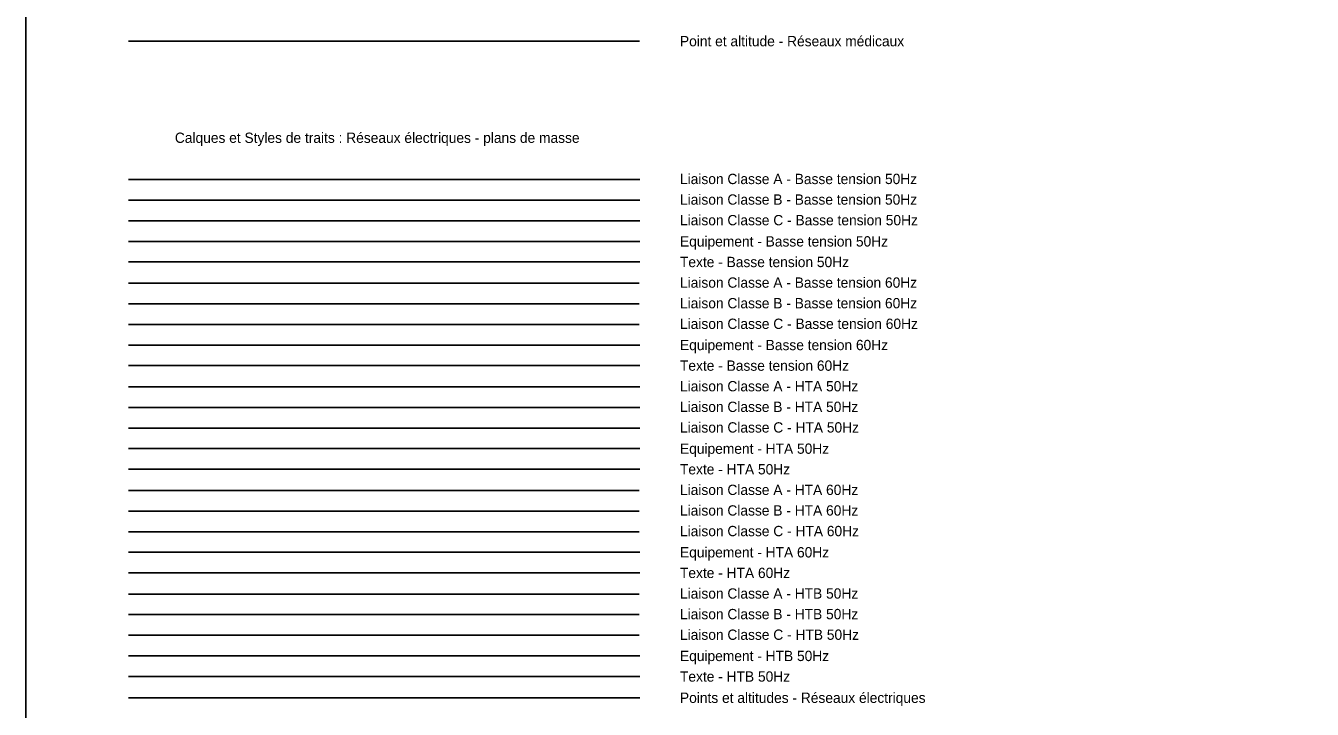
# Model space of a CAD drawing. Extents: x 703432 to 707394, y 7057985 to 7059523.
# Drawn here: x 707199.5 to 707262, y 7058568.9 to 7058602.1 of the extents above; entities that cross this region are included whole.
import ezdxf

# ---------------------------------------------------------------- set-up
doc = ezdxf.new("R2010")
doc.units = 0
for name, color, linetype in [('DH_CADRE -CARTOUCHE', 7, 'Continuous'), ('R_ELEC_ALT_POINT', 7, 'Continuous'), ('R_ELEC_BT_50HZ_EQUIP', 7, 'Continuous'), ('R_ELEC_BT_50HZ_LIAISON_CL_A', 7, 'Continuous'), ('R_ELEC_BT_50HZ_LIAISON_CL_B', 7, 'Continuous'), ('R_ELEC_BT_50HZ_LIAISON_CL_C', 7, 'Continuous'), ('R_ELEC_BT_50HZ_TEXTE', 7, 'Continuous'), ('R_ELEC_BT_60HZ_EQUIP', 7, 'Continuous'), ('R_ELEC_BT_60HZ_LIAISON_CL_A', 7, 'Continuous'), ('R_ELEC_BT_60HZ_LIAISON_CL_B', 7, 'Continuous'), ('R_ELEC_BT_60HZ_LIAISON_CL_C', 7, 'Continuous'), ('R_ELEC_BT_60HZ_TEXTE', 7, 'Continuous'), ('R_ELEC_HTA_50HZ_EQUIP', 7, 'Continuous'), ('R_ELEC_HTA_50HZ_LIAISON_CL_A', 7, 'Continuous'), ('R_ELEC_HTA_50HZ_LIAISON_CL_B', 7, 'Continuous'), ('R_ELEC_HTA_50HZ_LIAISON_CL_C', 7, 'Continuous'), ('R_ELEC_HTA_50HZ_TEXTE', 7, 'Continuous'), ('R_ELEC_HTA_60HZ_EQUIP', 7, 'Continuous'), ('R_ELEC_HTA_60HZ_LIAISON_CL_A', 7, 'Continuous'), ('R_ELEC_HTA_60HZ_LIAISON_CL_B', 7, 'Continuous'), ('R_ELEC_HTA_60HZ_LIAISON_CL_C', 7, 'Continuous'), ('R_ELEC_HTA_60HZ_TEXTE', 7, 'Continuous'), ('R_ELEC_HTB_50HZ_EQUIP', 7, 'Continuous'), ('R_ELEC_HTB_50HZ_LIAISON_CL_A', 7, 'Continuous'), ('R_ELEC_HTB_50HZ_LIAISON_CL_B', 7, 'Continuous'), ('R_ELEC_HTB_50HZ_LIAISON_CL_C', 7, 'Continuous'), ('R_ELEC_HTB_50HZ_TEXTE', 7, 'Continuous'), ('R_MED_ALT_POINT', 7, 'Continuous')]:
    doc.layers.add(name, color=color, linetype=linetype)

msp = doc.modelspace()

# ---------------------------------------------------------------- linework, layer by layer
at = {"layer": 'DH_CADRE -CARTOUCHE'}
msp.add_lwpolyline([(707199.469, 7058644.551), (707324.469, 7058644.551), (707324.469, 7058419.551), (707199.469, 7058419.551)], close=True, dxfattribs=at)
at = {"layer": 'R_ELEC_ALT_POINT'}
msp.add_line((707204.469, 7058569.453), (707229.298, 7058569.453), dxfattribs=at)
at = {"layer": 'R_ELEC_BT_50HZ_EQUIP'}
msp.add_line((707204.469, 7058591.608), (707229.298, 7058591.608), dxfattribs=at)
at = {"layer": 'R_ELEC_BT_50HZ_LIAISON_CL_A'}
msp.add_line((707204.469, 7058594.608), (707229.298, 7058594.608), dxfattribs=at)
at = {"layer": 'R_ELEC_BT_50HZ_LIAISON_CL_B'}
msp.add_line((707204.469, 7058593.608), (707229.298, 7058593.608), dxfattribs=at)
at = {"layer": 'R_ELEC_BT_50HZ_LIAISON_CL_C'}
msp.add_line((707204.469, 7058592.608), (707229.298, 7058592.608), dxfattribs=at)
at = {"layer": 'R_ELEC_BT_50HZ_TEXTE'}
msp.add_line((707204.469, 7058590.608), (707229.298, 7058590.608), dxfattribs=at)
at = {"layer": 'R_ELEC_BT_60HZ_EQUIP'}
msp.add_line((707204.469, 7058586.577), (707229.298, 7058586.577), dxfattribs=at)
at = {"layer": 'R_ELEC_BT_60HZ_LIAISON_CL_A'}
msp.add_line((707204.469, 7058589.577), (707229.262, 7058589.577), dxfattribs=at)
at = {"layer": 'R_ELEC_BT_60HZ_LIAISON_CL_B'}
msp.add_line((707204.469, 7058588.577), (707229.262, 7058588.577), dxfattribs=at)
at = {"layer": 'R_ELEC_BT_60HZ_LIAISON_CL_C'}
msp.add_line((707204.469, 7058587.577), (707229.262, 7058587.577), dxfattribs=at)
at = {"layer": 'R_ELEC_BT_60HZ_TEXTE'}
msp.add_line((707204.469, 7058585.577), (707229.298, 7058585.577), dxfattribs=at)
at = {"layer": 'R_ELEC_HTA_50HZ_EQUIP'}
msp.add_line((707204.469, 7058581.546), (707229.298, 7058581.546), dxfattribs=at)
at = {"layer": 'R_ELEC_HTA_50HZ_LIAISON_CL_A'}
msp.add_line((707204.469, 7058584.546), (707229.307, 7058584.546), dxfattribs=at)
at = {"layer": 'R_ELEC_HTA_50HZ_LIAISON_CL_B'}
msp.add_line((707204.469, 7058583.546), (707229.307, 7058583.546), dxfattribs=at)
at = {"layer": 'R_ELEC_HTA_50HZ_LIAISON_CL_C'}
msp.add_line((707204.469, 7058582.546), (707229.307, 7058582.546), dxfattribs=at)
at = {"layer": 'R_ELEC_HTA_50HZ_TEXTE'}
msp.add_line((707204.469, 7058580.546), (707229.298, 7058580.546), dxfattribs=at)
at = {"layer": 'R_ELEC_HTA_60HZ_EQUIP'}
msp.add_line((707204.469, 7058576.515), (707229.298, 7058576.515), dxfattribs=at)
at = {"layer": 'R_ELEC_HTA_60HZ_LIAISON_CL_A'}
msp.add_line((707204.469, 7058579.515), (707229.262, 7058579.515), dxfattribs=at)
at = {"layer": 'R_ELEC_HTA_60HZ_LIAISON_CL_B'}
msp.add_line((707204.469, 7058578.515), (707229.262, 7058578.515), dxfattribs=at)
at = {"layer": 'R_ELEC_HTA_60HZ_LIAISON_CL_C'}
msp.add_line((707204.469, 7058577.515), (707229.262, 7058577.515), dxfattribs=at)
at = {"layer": 'R_ELEC_HTA_60HZ_TEXTE'}
msp.add_line((707204.469, 7058575.515), (707229.298, 7058575.515), dxfattribs=at)
at = {"layer": 'R_ELEC_HTB_50HZ_EQUIP'}
msp.add_line((707204.469, 7058571.484), (707229.298, 7058571.484), dxfattribs=at)
at = {"layer": 'R_ELEC_HTB_50HZ_LIAISON_CL_A'}
msp.add_line((707204.469, 7058574.488), (707229.262, 7058574.488), dxfattribs=at)
at = {"layer": 'R_ELEC_HTB_50HZ_LIAISON_CL_B'}
msp.add_line((707204.469, 7058573.488), (707229.262, 7058573.488), dxfattribs=at)
at = {"layer": 'R_ELEC_HTB_50HZ_LIAISON_CL_C'}
msp.add_line((707204.469, 7058572.488), (707229.262, 7058572.488), dxfattribs=at)
at = {"layer": 'R_ELEC_HTB_50HZ_TEXTE'}
msp.add_line((707204.469, 7058570.484), (707229.298, 7058570.484), dxfattribs=at)
at = {"layer": 'R_MED_ALT_POINT'}
msp.add_line((707229.284, 7058601.329), (707204.469, 7058601.329), dxfattribs=at)

# ---------------------------------------------------------------- texts
at = {"layer": 'DH_CADRE -CARTOUCHE'}
msp.add_text(' Calques et Styles de traits : Réseaux électriques - plans de masse', height=0.5, dxfattribs=at).set_placement((707206.529, 7058596.389))
at = {"layer": 'R_ELEC_ALT_POINT'}
msp.add_text('Points et altitudes - Réseaux électriques', height=0.5, dxfattribs=at).set_placement((707231.252, 7058569.203))
at = {"layer": 'R_ELEC_BT_50HZ_EQUIP'}
msp.add_text('Equipement - Basse tension 50Hz', height=0.5, dxfattribs=at).set_placement((707231.252, 7058591.358))
at = {"layer": 'R_ELEC_BT_50HZ_LIAISON_CL_A'}
msp.add_text('Liaison Classe A - Basse tension 50Hz', height=0.5, dxfattribs=at).set_placement((707231.252, 7058594.389))
at = {"layer": 'R_ELEC_BT_50HZ_LIAISON_CL_B'}
msp.add_text('Liaison Classe B - Basse tension 50Hz', height=0.5, dxfattribs=at).set_placement((707231.252, 7058593.389))
at = {"layer": 'R_ELEC_BT_50HZ_LIAISON_CL_C'}
msp.add_text('Liaison Classe C - Basse tension 50Hz', height=0.5, dxfattribs=at).set_placement((707231.252, 7058592.389))
at = {"layer": 'R_ELEC_BT_50HZ_TEXTE'}
msp.add_text('Texte - Basse tension 50Hz', height=0.5, dxfattribs=at).set_placement((707231.252, 7058590.358))
at = {"layer": 'R_ELEC_BT_60HZ_EQUIP'}
msp.add_text('Equipement - Basse tension 60Hz', height=0.5, dxfattribs=at).set_placement((707231.252, 7058586.327))
at = {"layer": 'R_ELEC_BT_60HZ_LIAISON_CL_A'}
msp.add_text('Liaison Classe A - Basse tension 60Hz', height=0.5, dxfattribs=at).set_placement((707231.252, 7058589.358))
at = {"layer": 'R_ELEC_BT_60HZ_LIAISON_CL_B'}
msp.add_text('Liaison Classe B - Basse tension 60Hz', height=0.5, dxfattribs=at).set_placement((707231.252, 7058588.358))
at = {"layer": 'R_ELEC_BT_60HZ_LIAISON_CL_C'}
msp.add_text('Liaison Classe C - Basse tension 60Hz', height=0.5, dxfattribs=at).set_placement((707231.252, 7058587.358))
at = {"layer": 'R_ELEC_BT_60HZ_TEXTE'}
msp.add_text('Texte - Basse tension 60Hz', height=0.5, dxfattribs=at).set_placement((707231.252, 7058585.327))
at = {"layer": 'R_ELEC_HTA_50HZ_EQUIP'}
msp.add_text('Equipement - HTA 50Hz', height=0.5, dxfattribs=at).set_placement((707231.252, 7058581.296))
at = {"layer": 'R_ELEC_HTA_50HZ_LIAISON_CL_A'}
msp.add_text('Liaison Classe A - HTA 50Hz', height=0.5, dxfattribs=at).set_placement((707231.252, 7058584.327))
at = {"layer": 'R_ELEC_HTA_50HZ_LIAISON_CL_B'}
msp.add_text('Liaison Classe B - HTA 50Hz', height=0.5, dxfattribs=at).set_placement((707231.252, 7058583.327))
at = {"layer": 'R_ELEC_HTA_50HZ_LIAISON_CL_C'}
msp.add_text('Liaison Classe C - HTA 50Hz', height=0.5, dxfattribs=at).set_placement((707231.252, 7058582.327))
at = {"layer": 'R_ELEC_HTA_50HZ_TEXTE'}
msp.add_text('Texte - HTA 50Hz', height=0.5, dxfattribs=at).set_placement((707231.252, 7058580.296))
at = {"layer": 'R_ELEC_HTA_60HZ_EQUIP'}
msp.add_text('Equipement - HTA 60Hz', height=0.5, dxfattribs=at).set_placement((707231.252, 7058576.265))
at = {"layer": 'R_ELEC_HTA_60HZ_LIAISON_CL_A'}
msp.add_text('Liaison Classe A - HTA 60Hz', height=0.5, dxfattribs=at).set_placement((707231.252, 7058579.296))
at = {"layer": 'R_ELEC_HTA_60HZ_LIAISON_CL_B'}
msp.add_text('Liaison Classe B - HTA 60Hz', height=0.5, dxfattribs=at).set_placement((707231.252, 7058578.296))
at = {"layer": 'R_ELEC_HTA_60HZ_LIAISON_CL_C'}
msp.add_text('Liaison Classe C - HTA 60Hz', height=0.5, dxfattribs=at).set_placement((707231.252, 7058577.296))
at = {"layer": 'R_ELEC_HTA_60HZ_TEXTE'}
msp.add_text('Texte - HTA 60Hz', height=0.5, dxfattribs=at).set_placement((707231.252, 7058575.265))
at = {"layer": 'R_ELEC_HTB_50HZ_EQUIP'}
msp.add_text('Equipement - HTB 50Hz', height=0.5, dxfattribs=at).set_placement((707231.252, 7058571.234))
at = {"layer": 'R_ELEC_HTB_50HZ_LIAISON_CL_A'}
msp.add_text('Liaison Classe A - HTB 50Hz', height=0.5, dxfattribs=at).set_placement((707231.252, 7058574.265))
at = {"layer": 'R_ELEC_HTB_50HZ_LIAISON_CL_B'}
msp.add_text('Liaison Classe B - HTB 50Hz', height=0.5, dxfattribs=at).set_placement((707231.252, 7058573.265))
at = {"layer": 'R_ELEC_HTB_50HZ_LIAISON_CL_C'}
msp.add_text('Liaison Classe C - HTB 50Hz', height=0.5, dxfattribs=at).set_placement((707231.252, 7058572.265))
at = {"layer": 'R_ELEC_HTB_50HZ_TEXTE'}
msp.add_text('Texte - HTB 50Hz', height=0.5, dxfattribs=at).set_placement((707231.252, 7058570.234))
at = {"layer": 'R_MED_ALT_POINT'}
msp.add_text('Point et altitude - Réseaux médicaux', height=0.5, dxfattribs=at).set_placement((707231.252, 7058601.079))

doc.saveas('drawing.dxf')
